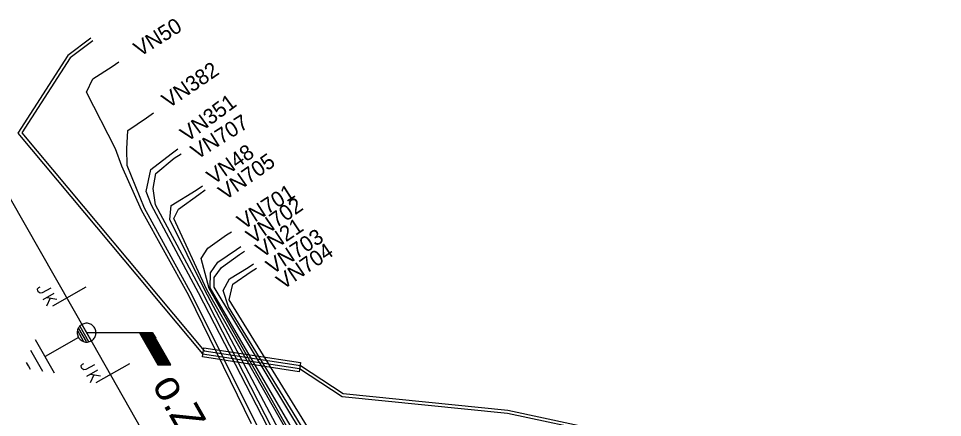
# Model space of a CAD drawing. Extents: x -545588 to -543214, y -1196037 to -1194452.
# Drawn here: x -545323 to -545262.7, y -1194878.9 to -1194853 of the extents above; entities that cross this region are included whole.
import ezdxf

# ---------------------------------------------------------------- set-up
doc = ezdxf.new("R2010")
doc.units = 0
for name, color, linetype in [('CIZÍ_NADZEM', 7, 'Continuous'), ('DOPLŇ_POPISY', 7, 'Continuous'), ('ELE_EON_POPIS', 7, 'Continuous'), ('Implicitní', 7, 'Continuous'), ('POL_ZNAČKA_PRACOVNÍ', 7, 'Continuous'), ('TECH_OCHR_PÁSMO_HRAN', 7, 'Continuous'), ('Vrstva 18', 7, 'Continuous'), ('Vrstva 20', 7, 'Continuous'), ('Vrstva 52', 7, 'Continuous'), ('Vrstva 54', 7, 'Continuous'), ('ZP_EON', 7, 'Continuous')]:
    doc.layers.add(name, color=color, linetype=linetype)

# ---------------------------------------------------------------- blocks, each defined once
blk = doc.blocks.new('VN840')
at = {"layer": 'POL_ZNAČKA_PRACOVNÍ'}
for points in [[(-0.009, 1.414), (-0.009, -1.086)], [(-1.092, -0.594), (-1.092, -1.243)], [(-0.678, -0.594), (-0.678, -1.421)], [(-0.678, -1.106), (-0.265, -0.594)], [(-1.505, -1.243), (-1.505, -1.145)], [(-0.541, -0.938), (-0.196, -1.421)], [(-1.476, -1.352), (-1.505, -1.243)], [(-1.328, -1.421), (-1.476, -1.352)], [(-1.269, -1.421), (-1.328, -1.421)], [(-1.131, -1.352), (-1.269, -1.421)], [(-1.092, -1.243), (-1.131, -1.352)]]:
    blk.add_lwpolyline(points, dxfattribs=at)
blk = doc.blocks.new('VN440')
at = {"layer": 'ELE_EON_POPIS'}
for points in [[(1.22, 0), (1.21, 0.13), (1.19, 0.25), (1.16, 0.38), (1.11, 0.5), (1.05, 0.61), (0.98, 0.72), (0.9, 0.82), (0.81, 0.91), (0.71, 0.99), (0.6, 1.06), (0.49, 1.12), (0.37, 1.16), (0.25, 1.2), (0.12, 1.22), (-0.01, 1.22), (-0.14, 1.22), (-0.26, 1.2), (-0.39, 1.16), (-0.51, 1.12), (-0.62, 1.06), (-0.73, 0.99), (-0.83, 0.91), (-0.92, 0.82), (-1, 0.72), (-1.07, 0.61), (-1.13, 0.5), (-1.18, 0.38), (-1.21, 0.25), (-1.23, 0.13), (-1.24, 0), (-1.23, -0.13), (-1.21, -0.26), (-1.18, -0.38), (-1.13, -0.5), (-1.07, -0.62), (-1, -0.73), (-0.92, -0.83), (-0.83, -0.92), (-0.73, -1), (-0.62, -1.07), (-0.51, -1.13), (-0.39, -1.17), (-0.26, -1.2), (-0.14, -1.23), (-0.01, -1.23), (0.12, -1.23), (0.25, -1.2), (0.37, -1.17), (0.49, -1.13), (0.6, -1.07), (0.71, -1), (0.81, -0.92), (0.9, -0.83), (0.98, -0.73), (1.05, -0.62), (1.11, -0.5), (1.16, -0.38), (1.19, -0.26), (1.21, -0.13), (1.22, 0)], [(-1.24, 0), (1.22, 0)], [(-1.18, -0.34), (1.1, -0.34)], [(-1.01, -0.63), (0.97, -0.63)], [(-0.74, -0.92), (0.68, -0.92)]]:
    blk.add_lwpolyline(points, dxfattribs=at)
blk = doc.blocks.new('VN810')
at = {"layer": 'POL_ZNAČKA_PRACOVNÍ'}
for points in [[(0.004, -1.247), (0.004, -3.747)], [(1.254, -3.747), (-1.246, -3.747)], [(0.772, -4.367), (-0.803, -4.367)], [(0.004, -4.997), (-0.252, -4.997)], [(0.27, -4.997), (0.004, -4.997)]]:
    blk.add_lwpolyline(points, dxfattribs=at)
blk = doc.blocks.new('VN001')
at = {"layer": 'Implicitní'}
for p, q in [((2.074, 3.631), (4.49, 3.631)), ((2.103, 3.681), (4.519, 3.681)), ((2.132, 3.731), (2.543, 3.731)), ((1.732, 3.031), (4.144, 3.031)), ((1.76, 3.081), (4.173, 3.081)), ((1.789, 3.131), (4.201, 3.131)), ((1.817, 3.181), (4.23, 3.181)), ((1.846, 3.231), (4.259, 3.231)), ((1.874, 3.281), (4.288, 3.281)), ((1.903, 3.331), (4.317, 3.331)), ((1.932, 3.381), (4.346, 3.381)), ((1.96, 3.431), (4.375, 3.431)), ((1.989, 3.481), (4.403, 3.481)), ((2.017, 3.531), (4.432, 3.531)), ((2.046, 3.581), (4.461, 3.581))]:
    blk.add_line(p, q, dxfattribs=at)
blk.add_lwpolyline([(2.132, 3.732), (0, 0)], dxfattribs=at)
blk.add_lwpolyline([(4.545, 3.727), (2.132, 3.732), (1.705, 2.984), (4.117, 2.985)], close=True, dxfattribs=at)

msp = doc.modelspace()

# ---------------------------------------------------------------- linework, layer by layer
at = {"layer": 'Vrstva 20'}
msp.add_lwpolyline([(-545310.985, -1194874.997), (-545310.894, -1194874.403), (-545304.595, -1194875.363), (-545304.686, -1194875.957)], close=True, dxfattribs=at)
at = {"layer": 'Vrstva 52'}
for points in [[(-545318.54, -1194873.42), (-545325.567, -1194861.127)], [(-545295.62, -1194964.78), (-545301.623, -1194904.598), (-545301.79, -1194902.92), (-545302.625, -1194901.45), (-545318.54, -1194873.42)]]:
    msp.add_lwpolyline(points, dxfattribs=at)
at = {"layer": 'ZP_EON'}
for points in [[(-545318.26, -1194854.24), (-545319.764, -1194855.371), (-545323.024, -1194860.428), (-545310.992, -1194874.793), (-545304.676, -1194875.756), (-545301.884, -1194877.567), (-545291.116, -1194878.669), (-545284.779, -1194880.016), (-545281.704, -1194881.218), (-545279.668, -1194881.426), (-545278.229, -1194883.012), (-545276.934, -1194884.085), (-545275.478, -1194884.788), (-545274.362, -1194885.487), (-545273.991, -1194886.484), (-545274.22, -1194889.287), (-545274.099, -1194895.186), (-545272.737, -1194896.371), (-545268.613, -1194897.38), (-545261.946, -1194897.55)], [(-545318.145, -1194854.404), (-545319.616, -1194855.509), (-545322.776, -1194860.412), (-545310.888, -1194874.607), (-545304.604, -1194875.564), (-545301.816, -1194877.373), (-545291.084, -1194878.471), (-545284.721, -1194879.824), (-545281.656, -1194881.022), (-545279.572, -1194881.234), (-545278.091, -1194882.868), (-545276.826, -1194883.915), (-545275.382, -1194884.612), (-545274.198, -1194885.353), (-545273.789, -1194886.456), (-545274.02, -1194889.293), (-545273.901, -1194895.094), (-545272.643, -1194896.189), (-545268.587, -1194897.18), (-545261.954, -1194897.35)], [(-545307.79, -1194879.36), (-545311.89, -1194871), (-545314.97, -1194865.44), (-545316.25, -1194862.58), (-545316.66, -1194861.44), (-545318.56, -1194857.75), (-545318.14, -1194856.88), (-545316.87, -1194856.09), (-545316.451, -1194855.779)], [(-545307.45, -1194879.44), (-545311.66, -1194870.97), (-545314.76, -1194865.31), (-545315.91, -1194862.52), (-545315.92, -1194861.44), (-545315.86, -1194860.26), (-545314.64, -1194859.43), (-545314.186, -1194859.097)], [(-545248.72, -1194905.18), (-545267.26, -1194906.67), (-545268, -1194906.41), (-545269.32, -1194904.93), (-545269.81, -1194901), (-545270.36, -1194899.57), (-545272.04, -1194898.4), (-545274.071, -1194897.475), (-545276.184, -1194896.005), (-545276.201, -1194894.148), (-545276.316, -1194889.638), (-545276.51, -1194888.43), (-545277.65, -1194886.42), (-545278.88, -1194885.77), (-545283.582, -1194885.46), (-545299.484, -1194885.308), (-545303.47, -1194884.61), (-545304.7, -1194883.47), (-545311.25, -1194870.82), (-545314.32, -1194865.11), (-545314.67, -1194864.22), (-545314.35, -1194862.78), (-545313.03, -1194861.76), (-545312.597, -1194861.441)], [(-545306.44, -1194879.65), (-545311.05, -1194870.68), (-545314.05, -1194865.09), (-545314.2, -1194864.03), (-545314.03, -1194863.06), (-545312.84, -1194862.05), (-545312.379, -1194861.759)], [(-545248.73, -1194904.4), (-545267.223, -1194905.96), (-545268.63, -1194904.731), (-545268.916, -1194901.286), (-545269.859, -1194899.284), (-545271.71, -1194897.9), (-545273.79, -1194897.04), (-545275.509, -1194895.899), (-545275.66, -1194894.15), (-545275.76, -1194889.647), (-545275.796, -1194888.232), (-545276.399, -1194885.93), (-545278.863, -1194885.175), (-545283.778, -1194885.175), (-545299.41, -1194885.02), (-545303.33, -1194884.18), (-545304.18, -1194883.1), (-545306.02, -1194879.74), (-545310.87, -1194870.61), (-545313.129, -1194866.04), (-545313.03, -1194865.13), (-545311.41, -1194864.14), (-545310.989, -1194863.845)], [(-545248.71, -1194904.72), (-545267.29, -1194906.26), (-545268.92, -1194904.81), (-545269.44, -1194900.94), (-545270.064, -1194899.408), (-545271.8, -1194898.11), (-545274.04, -1194897.2), (-545275.7, -1194896.04), (-545275.876, -1194894.165), (-545275.996, -1194889.643), (-545276.063, -1194888.347), (-545276.815, -1194886.164), (-545278.872, -1194884.953), (-545283.76, -1194885.07), (-545299.43, -1194884.82), (-545303.32, -1194883.88), (-545304.01, -1194882.97), (-545305.45, -1194879.87), (-545310.7, -1194870.63), (-545312.86, -1194865.98), (-545312.55, -1194865.37), (-545311.22, -1194864.41), (-545310.81, -1194864.123)], [(-545248.68, -1194904.56), (-545267.25, -1194906.09), (-545268.77, -1194904.77), (-545269.023, -1194901.357), (-545269.966, -1194899.355), (-545271.75, -1194898), (-545273.96, -1194897.15), (-545275.589, -1194895.975), (-545275.769, -1194894.17), (-545275.867, -1194889.647), (-545275.912, -1194888.298), (-545276.584, -1194886.092), (-545278.916, -1194884.757), (-545283.795, -1194884.953), (-545299.42, -1194884.56), (-545303.3, -1194883.65), (-545303.81, -1194882.81), (-545305.28, -1194879.91), (-545310.56, -1194870.54), (-545311.07, -1194868.58), (-545310.64, -1194867.91), (-545309.43, -1194867.05), (-545309.101, -1194866.84)], [(-545248.73, -1194904.26), (-545267.223, -1194905.818), (-545268.497, -1194904.695), (-545268.8, -1194901.233), (-545269.753, -1194899.204), (-545271.62, -1194897.81), (-545273.79, -1194896.9), (-545275.38, -1194895.84), (-545275.555, -1194894.192), (-545275.653, -1194889.647), (-545275.689, -1194888.08), (-545276.21, -1194885.807), (-545278.95, -1194884.58), (-545283.83, -1194884.81), (-545299.34, -1194884.41), (-545303.2, -1194883.43), (-545303.65, -1194882.76), (-545304.96, -1194879.97), (-545310.48, -1194870.49), (-545310.47, -1194869.52), (-545309.98, -1194868.83), (-545308.78, -1194868), (-545308.485, -1194867.803)], [(-545248.8, -1194904.02), (-545267.18, -1194905.57), (-545268.07, -1194904.61), (-545268.66, -1194901.21), (-545269.54, -1194899.09), (-545271.53, -1194897.66), (-545273.76, -1194896.79), (-545275.07, -1194895.87), (-545275.457, -1194894.179), (-545275.546, -1194889.656), (-545275.582, -1194888.027), (-545276.031, -1194885.692), (-545278.94, -1194884.43), (-545283.99, -1194884.66), (-545299.36, -1194884.26), (-545303.04, -1194882.99), (-545303.27, -1194882.6), (-545304.4, -1194880.12), (-545310.24, -1194870.45), (-545310.23, -1194869.82), (-545309.76, -1194869.17), (-545308.57, -1194868.32), (-545308.257, -1194868.111)], [(-545248.86, -1194903.88), (-545267.1, -1194905.41), (-545267.75, -1194904.54), (-545268.5, -1194901.02), (-545269.22, -1194899.03), (-545271.359, -1194897.6), (-545273.69, -1194896.71), (-545274.99, -1194895.81), (-545275.36, -1194894.17), (-545275.44, -1194889.63), (-545275.449, -1194888.027), (-545275.82, -1194885.54), (-545278.92, -1194884.25), (-545284.13, -1194884.44), (-545299.28, -1194884.04), (-545302.83, -1194882.74), (-545304.12, -1194880.18), (-545309.29, -1194871.74), (-545309.64, -1194870.67), (-545309.23, -1194869.91), (-545308.02, -1194869.17), (-545307.661, -1194868.936)], [(-545248.84, -1194903.69), (-545267.05, -1194905.12), (-545267.37, -1194904.62), (-545268.19, -1194900.93), (-545268.92, -1194898.92), (-545271.28, -1194897.4), (-545273.52, -1194896.55), (-545275.957, -1194896.094), (-545276.077, -1194895.999), (-545276.085, -1194894.152), (-545276.214, -1194889.643), (-545274.84, -1194888.2), (-545275.24, -1194885.1), (-545278.81, -1194884.1), (-545284.21, -1194884.13), (-545299.29, -1194883.82), (-545302.55, -1194882.54), (-545303.68, -1194880.28), (-545309.26, -1194871.27), (-545309.01, -1194870.25), (-545307.81, -1194869.43), (-545307.472, -1194869.214)]]:
    msp.add_lwpolyline(points, dxfattribs=at)

# ---------------------------------------------------------------- block references
at = {"layer": 'DOPLŇ_POPISY', "xscale": 0.5, "yscale": 0.5, "rotation": -60.248344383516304}
msp.add_blockref('VN440', (-545318.541, -1194873.421), dxfattribs=at)
at = {"layer": 'POL_ZNAČKA_PRACOVNÍ', "rotation": -60.24428055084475}
msp.add_blockref('VN810', (-545317.997, -1194873.1), dxfattribs=at)
at = {"layer": 'TECH_OCHR_PÁSMO_HRAN', "rotation": -60.245422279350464}
msp.add_blockref('VN001', (-545318.54, -1194873.419), dxfattribs=at)
at = {"layer": 'Vrstva 18'}
for p, rotation in [((-545319.829, -1194871.164), -60.24658609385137), ((-545316.984, -1194876.162), -60.412235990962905)]:
    msp.add_blockref('VN840', p, dxfattribs=dict(at, rotation=rotation))

# ---------------------------------------------------------------- texts
at = {"layer": 'CIZÍ_NADZEM'}
for s, rotation, p in [('VN50', 31.884, (-545315.078, -1194855.474)), ('VN382', 34.229, (-545313.203, -1194858.836)), ('VN351', 36.38, (-545311.979, -1194861.035)), ('VN707', 32.262, (-545311.346, -1194862.172)), ('VN48', 35.019, (-545310.27, -1194863.811)), ('VN705', 34.992, (-545309.512, -1194864.827)), ('VN701', 32.55, (-545308.323, -1194866.734)), ('VN702', 34.67, (-545307.707, -1194867.683)), ('VN21', 33.732, (-545307.097, -1194868.572)), ('VN703', 33.097, (-545306.43, -1194869.654)), ('VN704', 34.346, (-545305.744, -1194870.645))]:
    msp.add_text(s, height=1, rotation=rotation, dxfattribs=at).set_placement(p)
at = {"layer": 'Vrstva 54'}
msp.add_text('o.Zarazice VS', height=2, rotation=299.588, dxfattribs=at).set_placement((-545314.315, -1194876.802))

doc.saveas('drawing.dxf')
